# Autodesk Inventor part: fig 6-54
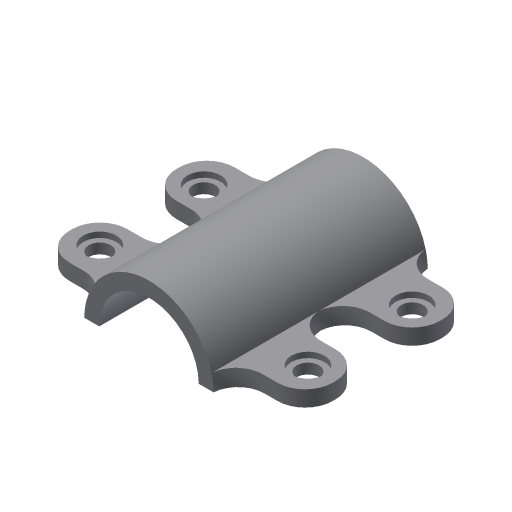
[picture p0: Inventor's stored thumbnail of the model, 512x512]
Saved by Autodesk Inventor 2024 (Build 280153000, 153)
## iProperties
Created: 2004-05
Part Number: fig 6-54
Document SubType Name: Modeling
Designer: CADCIM Technologies
Manufacturer: Standard
Standards Organization: Custom
Density: 1 g/cm^3
Material: Generic
Appearance: Default
Author: CADCIM Technologies
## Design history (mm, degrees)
sketch "Sketch2"
  geometry: L1 (23.378, 0)-(17.996, 0); L2 (-17.996, 0)-(-23.378, 0); A1 r 23.378 centre (0, 0) between (23.378, 0) and (-23.378, 0); A2 r 17.996 centre (0, 0) between (17.996, 0) and (-17.996, 0)
  constraints: 4 end point, 4 point on circle, 2 centre point, 1 collinear, 1 horizontal
extrude "Extrusion1" new body sketch "Sketch2" stored distance "d0" = 38.75; taper "d1" = 0 deg
sketch "Sketch3"
  geometry: L1 (23.378, 0)-(17.996, 0); L2 (-17.996, 0)-(-23.378, 0) reference; L3 (-23.378, 0)-(-47.662, 0); L4 (-47.662, 0)-(-47.662, 5.722); L5 (-47.662, 5.722)-(-22.667, 5.722); A1 r 17.996 centre (0, 0) between (17.996, 0) and (-17.996, 0) reference; A2 r 23.378 centre (0, 0) between (23.378, 0) and (-23.378, 0) reference; 1 further point
  constraints: 10 end point, 5 point on circle, 2 centre point, 1 collinear, 1 horizontal, 1 midpoint, 1 parallel, 1 perpendicular, 3 other
extrude "Extrusion2" join sketch "Sketch3" stored distance "d2" = 21; taper "d3" = 0 deg
fillet "Fillet1" dims "d4" = 10
hole "Hole1" diameter "d7" = 8; stored, may be unused: countersink angle "d11" = 90 deg, drill point angle "d13" = 118 deg; dims "d5" = 10, "d6" = 10, "d8" = 6, "d9" = 12, "d10" = 2, "d12" = 12
fillet "Fillet2" dims "d14" = 9.5
mirror "Mirror1"
mirror "Mirror2"
body "Solid1"
node "Sketch1"
